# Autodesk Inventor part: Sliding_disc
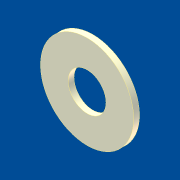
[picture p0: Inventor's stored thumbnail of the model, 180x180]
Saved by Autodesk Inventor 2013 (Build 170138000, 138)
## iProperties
Shininess: 31.0
Length Units: 11269
Angle Units: 11279
Time Units: 11290
Mass Units: 11283
Length Display Precision: 3
Angle Display Precision: 2
Created: 2001-04
Part Number: Sliding_disc
Material: Standard
Document SubType Name: Modellieren
Designer: dl
Density: 1 g/cm^3
Density: 0.0
Volumn: 0.0
Area: 0.0
PropertySet Name: Model Information
Control State: 0
Master: False
Checked Out: False
Author: dl
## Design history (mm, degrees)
body "Solid1"
sketch "Sketch1"
  geometry: C1 r 8 at (0, 0); C2 r 3.25 at (0, 0)
  constraints: 2 centre point, 1 coincident
  dimensions: "d0" = 16 diameter of C1; "d1" = 6.5 diameter of C2
extrude "Extrusion1" new body sketch "Sketch1" distance "d2" = 1; taper "d3" = 0 deg
